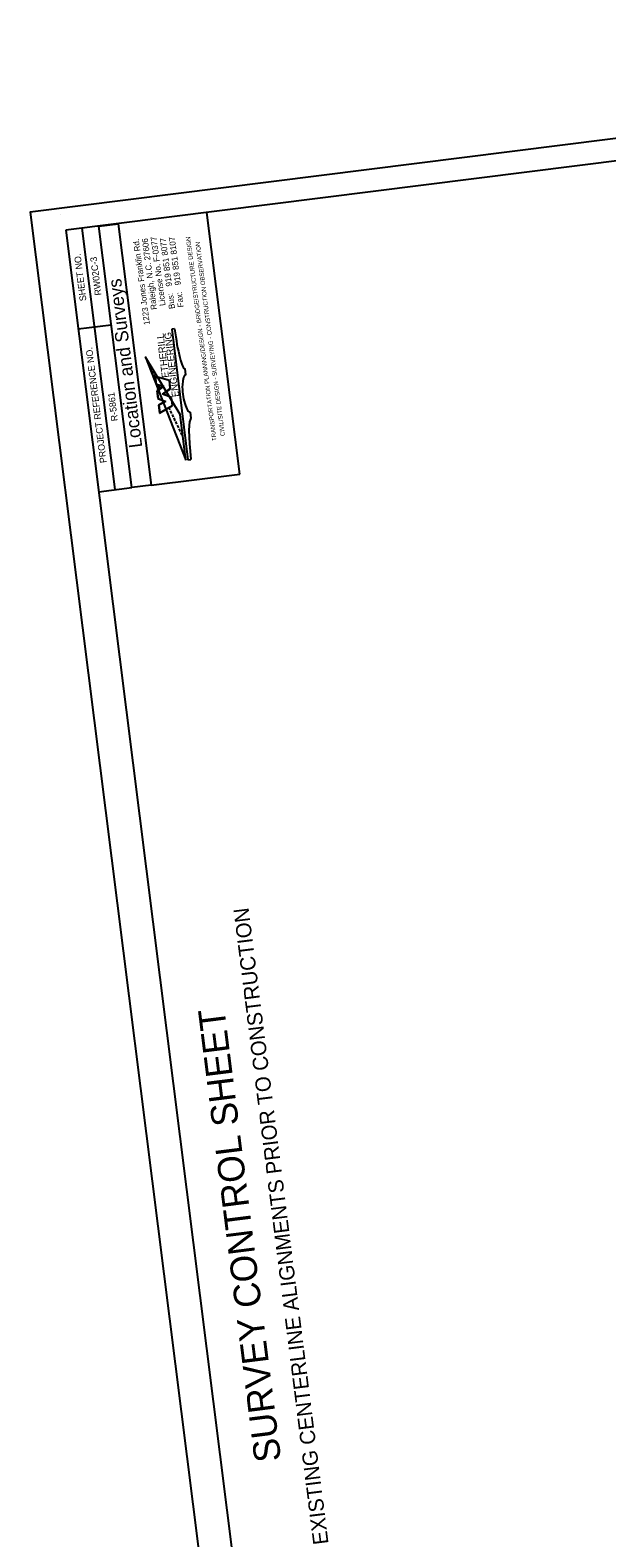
# Model space of a CAD drawing. Extents: x 477009 to 479892, y 492858 to 496862.
# Drawn here: x 477009 to 477973, y 494341 to 496862 of the extents above; entities that cross this region are included whole.
import ezdxf

# ---------------------------------------------------------------- set-up
doc = ezdxf.new("R2010")
doc.units = 0
for name, color, linetype in [('CTL Sheet Border CELL', 7, 'Continuous'), ('CTL Sheet Notes CELL', 7, 'Continuous'), ('Sheet Plot Border Outside CELL', 7, 'Continuous')]:
    doc.layers.add(name, color=color, linetype=linetype)

msp = doc.modelspace()

# ---------------------------------------------------------------- linework, layer by layer
at = {"layer": 'CTL Sheet Border CELL'}
for p, q in [((477009.3, 496557.8), (477009.3, 496557.8)), ((477059.9, 496554.2), (477059.9, 496554.2)), ((477059.9, 496554.2), (477059.9, 496554.2)), ((477359.5, 496119.9), (477304.5, 496557)), ((477151.5, 496093.8), (477096.5, 496530.9)), ((477089.8, 496362.6), (477144.7, 496369.5)), ((477124, 496090.3), (477179, 496097.2)), ((477211.3, 496101.3), (477359.5, 496119.9))]:
    msp.add_line(p, q, dxfattribs=at)
for points in [[(477068.9, 496527.4), (477483.7, 493231.4), (479790.9, 493521.7), (479376.1, 496817.7)], [(477179, 496097.2), (477124, 496534.3), (477156.3, 496538.4), (477211.3, 496101.3)]]:
    msp.add_lwpolyline(points, close=True, dxfattribs=at)
at = {"layer": 'CTL Sheet Notes CELL'}
for p, q in [((477250.8, 496362.5), (477245.9, 496361.9)), ((477245.9, 496361.9), (477273, 496143.6)), ((477215.1, 496287.6), (477213, 496292.1)), ((477217.9, 496281.6), (477215.8, 496286.1)), ((477218.1, 496283.2), (477219.7, 496270.1)), ((477242, 496276), (477218.5, 496282.7)), ((477218.5, 496282.7), (477220, 496270.3)), ((477243.6, 496262.8), (477242, 496276)), ((477244, 496262.6), (477242.3, 496276.3)), ((477269.6, 496285.9), (477268.4, 496295.8)), ((477219.7, 496270.1), (477232, 496266.5)), ((477220, 496270.3), (477232.8, 496266.7)), ((477232, 496266.5), (477221.1, 496258.9)), ((477221.1, 496258.9), (477222.7, 496246.1)), ((477232.8, 496266.7), (477221.5, 496258.7)), ((477221.5, 496258.7), (477223, 496246.3)), ((477226.4, 496263.4), (477224.3, 496268)), ((477230.5, 496253.6), (477243.6, 496262.8)), ((477245.5, 496247.9), (477230.5, 496253.6)), ((477231.2, 496253.7), (477244, 496262.6)), ((477245.8, 496248.1), (477231.2, 496253.7)), ((477247.1, 496234.7), (477245.5, 496247.9)), ((477247.5, 496234.5), (477245.8, 496248.1)), ((477222.7, 496246.1), (477235.1, 496241.4)), ((477223, 496246.3), (477235.9, 496241.4)), ((477235.1, 496241.4), (477224.1, 496234.9)), ((477224.1, 496234.9), (477225.7, 496221.8)), ((477235.9, 496241.4), (477224.4, 496234.8)), ((477224.4, 496234.8), (477226, 496222.4)), ((477225.7, 496221.8), (477247.5, 496234.5)), ((477226, 496222.4), (477247.1, 496234.7)), ((477243.4, 496227.2), (477241.3, 496231.8)), ((477246.3, 496221.2), (477244.1, 496225.7)), ((477278.7, 496213.2), (477277.4, 496223.1)), ((477249.1, 496215.2), (477247, 496219.7)), ((477251.9, 496209.1), (477249.8, 496213.6)), ((477254.7, 496203.1), (477252.6, 496207.6)), ((477257.6, 496197), (477255.5, 496201.6)), ((477260.4, 496191), (477258.3, 496195.5)), ((477263.2, 496185), (477261.1, 496189.5)), ((477273, 496143.6), (477278, 496144.2))]:
    msp.add_line(p, q, dxfattribs=at)
msp.add_lwpolyline([(477269.7, 496143.2), (477260.3, 496219.3), (477202, 496315.5)], close=True, dxfattribs=at)
msp.add_lwpolyline([(477242.3, 496276.3), (477241.9, 496276.4), (477218.1, 496283.2)], dxfattribs=at)
for centre, major_axis, ratio, start_param, end_param in [((477259.9, 496363.7), (-8.4, 67.8), 0.134146, 1.570796, 3.141593), ((477273.5, 496254.5), (-3.9, 31.4), 0.289474, 0, 3.141593), ((477287.1, 496145.3), (8.4, -67.8), 0.134146, 3.141593, 4.712389)]:
    msp.add_ellipse(centre, major_axis=major_axis, ratio=ratio, start_param=start_param, end_param=end_param, dxfattribs=at)
at = {"layer": 'Sheet Plot Border Outside CELL'}
msp.add_lwpolyline([(479892, 493161.7), (479426.4, 496862), (477009.3, 496557.8), (477475, 492857.5)], close=True, dxfattribs=at)

# ---------------------------------------------------------------- texts
at = {"layer": 'CTL Sheet Border CELL'}
for s, height, p in [('SHEET NO.', 11.07, (477103.4, 496409.7)), ('RW02C-3', 11.07, (477128.6, 496419.1)), ('Location and Surveys', 22.147, (477196.8, 496165)), ('PROJECT REFERENCE NO.', 11.074, (477137.2, 496139)), ('R-5861', 11.07, (477156, 496208.9)), ('W/  EXISTING CENTERLINE ALIGNMENTS PRIOR TO CONSTRUCTION', 25.469, (477515.7, 494271.5)), ('SURVEY CONTROL SHEET ', 44.294, (477429, 494470.9))]:
    msp.add_text(s, height=height, rotation=97.1725, dxfattribs=at).set_placement(p)
at = {"layer": 'CTL Sheet Notes CELL'}
for s, height, rotation, p in [('1223 Jones Franklin Rd. ', 10, 97.4175, (477209.5, 496369.7)), ('Raleigh, N.C. 27606', 10, 97.4175, (477221.3, 496395.2)), ('License No. F-0377', 10, 97.4175, (477235.6, 496401.6)), ('Bus:   919 851 8077', 10, 97.4175, (477251.4, 496396.5)), ('Fax:   919 851 8107', 10, 97.4175, (477266.2, 496399.1)), ('TRANSPORTATION PLANNING/DESIGN - BRIDGE/STRUCTURE DESIGN', 7.333, 97.4175, (477321.1, 496175.7)), ('CIVIL/SITE DESIGN - SURVEYING - CONSTRUCTION OBSERVATION', 7.333, 97.4175, (477334.9, 496183.9)), ('ETHERILL', 11.67, 97.0911, (477241.3, 496281.5)), ('ENGINEERING', 11.667, 97.0911, (477258.2, 496249.4))]:
    msp.add_text(s, height=height, rotation=rotation, dxfattribs=at).set_placement(p)

doc.saveas('drawing.dxf')
